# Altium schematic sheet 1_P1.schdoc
size 307 x 218 mm; Symbol: Drawing-Symbol_A4; Device: Drawing-Symbol_A4; Company: 嘉立创EDA; Version: V1.0; Page Size: A4; @Project Name: 12V9V转5V3.3V DC-DC; @Page Count: 1; @Update Date: 2025-03-15; @Create Date: 2025-03-13; @Schematic Name: Schematic1; @Page No: 1; @Page Name: P1; @Create Time: 11:37:29; @Update Time: 17:38:55; Width: 1170; Height: 825; Region Start: 1; X Region Count: 6; Y Region Count: 4; Blade Width: 10; Title Block Position: 3; @Board Name: Board1
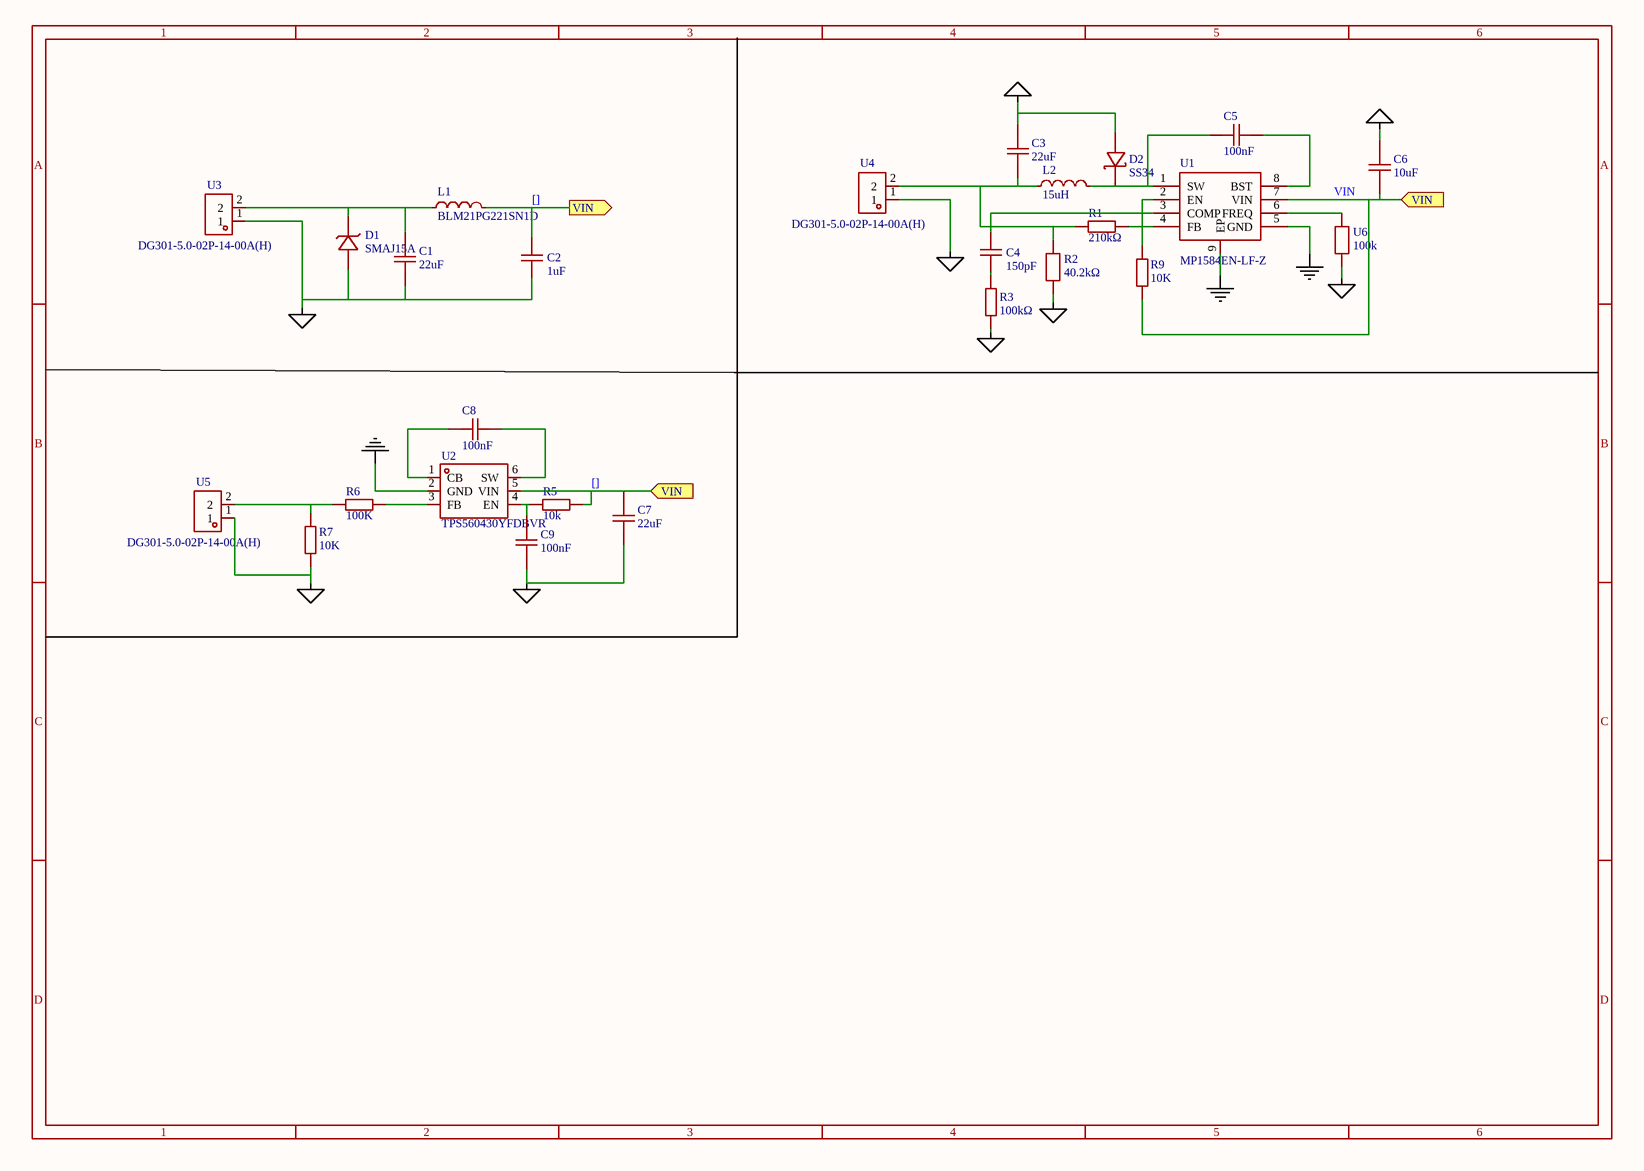
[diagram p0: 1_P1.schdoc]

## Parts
C1  22uF  [C2220]
C2  1uF  [C0805]
C3  22uF  [C1206]
C4  150pF  [C0805]
C5  100nF  [C0805]
C6  10uF  [C1206]
C7  22uF  [C0603]
C8  100nF  [C0603]
C9  100nF  [C0603]
D1  SMAJ15A  [SMA_L4.3-W2.6-LS5.0-RD]
D2  SS34  [SMC_L6.9-W5.9-LS7.9-RD]
L1  BLM21PG221SN1D  [L0805]
L2  15uH  [IND-SMD_L7.3-W6.8]
R1  210kΩ  [R1206]
R2  40.2kΩ  [R1206]
R3  100kΩ  [R0805]
R5  10k  [R0603]
R6  100K  [R0805]
R7  10K  [R0805]
R9  10K  [R1206]
U1  MP1584EN-LF-Z  [SOIC-8_L5.0-W4.0-P1.27-LS6.0-BL-EP2.0]
U2  TPS560430YFDBVR  [SOT-23-6_L2.9-W1.6-P0.95-LS2.8-BR]
U3  DG301-5.0-02P-14-00A(H)  [CONN-TH_DEGSON_DG301-5.0-02P]
U4  DG301-5.0-02P-14-00A(H)  [CONN-TH_DEGSON_DG301-5.0-02P]
U5  DG301-5.0-02P-14-00A(H)  [CONN-TH_DEGSON_DG301-5.0-02P]
U6  100k  [R0805]

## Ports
VIN (in), VIN (out)

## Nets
AGND: C1.1 C2.1 C3.2 C6.2 C7.1 C9.1 D1.2(A) D2.2(A) R2.1 R3.1 R7.1 U3.1 U4.1 U5.1 U6.1
GND: U1.5(GND) U1.9(EP) U2.2(GND)
[]: C2.2 C6.1 C7.2 L1.2 R5.1 R9.1 U1.7(VIN) U2.5(VIN) ; port VIN  [also labelled VIN]
NetC1_2: C1.2 D1.1(K) L1.1 U3.2
NetC3_1: C3.1 L2.1 R1.1 R2.2 U4.2
NetC4_1: C4.1 R3.2
NetC4_2: C4.2 U1.3(COMP)
NetC5_1: C5.1 U1.8(BST)
NetC5_2: C5.2 D2.1(C) L2.2 U1.1(SW)
NetC8_1: C8.1 U2.6(SW)
NetC8_2: C8.2 U2.1(CB)
NetC9_2: C9.2 R5.2 U2.4(EN)
NetR1_2: R1.2 U1.4(FB)
NetR6_1: R6.1 U2.3(FB)
NetR6_2: R6.2 R7.2 U5.2
NetR9_2: R9.2 U1.2(EN)
NetU1_6: U1.6(FREQ) U6.2

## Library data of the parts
C1 = FS55X226K500EHG: Manufacturer: PSA(信昌电陶); Add into BOM: yes; Tolerance: ±10%; Voltage Rating: 50V; Temperature Coefficient: X7R
C2 = CL21B105KBFNNNE: Manufacturer: SAMSUNG(三星); Add into BOM: yes; Tolerance: ±10%; Voltage Rated: 50V; Temperature Coefficient: X7R
C3 = GCM31CR70J226KE23L: Manufacturer: muRata(村田); Add into BOM: yes; Tolerance: ±10%; Voltage Rated: 6.3V; Temperature Coefficient: X7R
C4 = CC0805JRNPO9BN151: Manufacturer: YAGEO(国巨); Add into BOM: yes; Tolerance: ±5%; Voltage Rated: 50V; Temperature Coefficient: NP0
C5 = CAP_0805: Symbol: CapAcitance; Convert to PCB: yes
C6 = HGC1206R5106K500NSPJ: Manufacturer: Chinocera(华瓷); Add into BOM: yes; Tolerance: ±10%; Voltage Rated: 50V; Temperature Coefficient: X5R
C7 = CL10A226MP8NUNE: Manufacturer: SAMSUNG(三星); Add into BOM: yes; Tolerance: ±20%; Voltage Rated: 10V; Temperature Coefficient: X5R
C8 C9 = CAP_0603: Symbol: CapAcitance; Convert to PCB: yes
D1 = SMAJ15A_C19077535: Manufacturer: 宏嘉诚; Add into BOM: yes; Polarity: 单向; Reverse Stand-Off Voltage (Vrwm): 15V; Clamping Voltage: 24.4V; Peak Pulse Current (Ipp): 16.4A; Peak Pulse Power Dissipation (Ppp): 400W; Voltage - Breakdown: 16.7V; Reverse Leakage Current (Ir): 1uA; Number of Channels: 单路; Type: TVS
D2 = SS34_C154551: Manufacturer: onsemi(安森美); Add into BOM: yes; Forward Voltage (Vf@If): 500mV@3A; Reverse Voltage (Vr): 40V; Rectified Current: 3A; Reverse Leakage Current (Ir): 500uA@40V
L1 = BLM21PG221SN1D: Manufacturer: muRata(村田); Add into BOM: yes; Impedance @ Frequency: 220Ω@100MHz; Tolerance: ±25%; DC Resistance: 45mΩ; Current Rating: 2A; Circuits: 1
L2 = MWSA0603S-150MT: Manufacturer: Sunlord(顺络); Add into BOM: yes; Tolerance: ±20%; Rated Current: 3A; Current - Saturation(Isat): 4A; DC Resistance(DCR): 113mΩ
R1 = 1206W4F2103T5E: Manufacturer: UNI-ROYAL(厚声); Add into BOM: yes; Tolerance: ±1%; Power(Watts): 250mW; Overload Voltage (Max): 200V; Temperature Coefficient: ±100ppm/℃
R2 = FRC1206F4022TS: Manufacturer: FOJAN(富捷); Add into BOM: yes; Tolerance: ±1%; Power(Watts): 250mW; Overload Voltage (Max): 200V; Temperature Coefficient: ±100ppm/℃
R3 = 0805W8F1003T5E: Manufacturer: UNI-ROYAL(厚声); Symbol: 0805W8F1003T5E_C149504; Add into BOM: yes; Tolerance: ±1%; Power(Watts): 125mW; Overload Voltage (Max): 150V; Temperature Coefficient: ±100ppm/℃
R5 = Res_0603: Symbol: 电阻; Convert to PCB: yes
R6 R7 = Res_0805: Symbol: 电阻; Convert to PCB: yes
R9 = Res_1206: Symbol: 电阻; Add into BOM: yes
U1 = MP1584EN-LF-Z: Manufacturer: MPS(芯源); Add into BOM: yes; Function: 降压型; Output Type: 固定; Input Voltage: 4.5V~28V; Output Voltage: 800mV~25V; Output Current: 3A; Switching Frequency: 100kHz~1.5MHz; Synchronous Rectification: 否; Number of Outputs: 1; Topology: 降压式; Quiescent Current (Iq): 100uA; Switch tube (built-in/external): 内置
U2 = TPS560430YFDBVR: Manufacturer: TI(德州仪器); Add into BOM: yes; Function: 降压型; Input Voltage: 4V~36V; Output Voltage: 1V~34.2V; Output Current: 600mA; Switching Frequency: 2.1MHz; Synchronous Rectification: 是; Number of Outputs: 1; Topology: 降压式; Switch tube (built-in/external): 内置
U3-U5 = DG301-5.0-02P-14-00A(H): Manufacturer: DEGSON(高正/高松); Add into BOM: yes; Pitch: 5mm; Number of PINs Per Row: 2
U6 = FRC0805F2492TS: Manufacturer: FOJAN(富捷); Add into BOM: yes; Tolerance: ±1%; Power(Watts): 125mW; Overload Voltage (Max): 150V; Temperature Coefficient: ±100ppm/℃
